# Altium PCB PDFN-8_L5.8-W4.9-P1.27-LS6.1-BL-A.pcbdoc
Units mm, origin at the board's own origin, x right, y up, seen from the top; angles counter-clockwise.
Board outline 18.23 x 19.67 mm, 2 copper layers (Top Layer, Bottom Layer), stack 0 mm thick; 1 components, 0 nets, 9 pads, 0 vias.
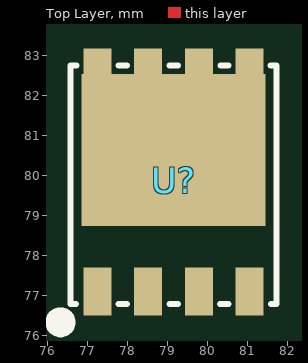
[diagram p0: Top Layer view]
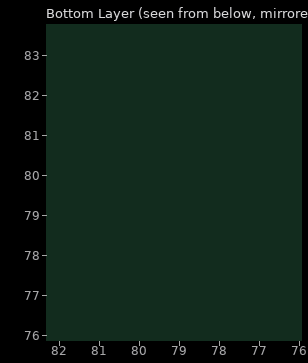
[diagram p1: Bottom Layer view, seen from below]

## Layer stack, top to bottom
Top Layer: signal copper (thickness not stored)
Bottom Layer: signal copper (thickness not stored)

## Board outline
88.08,69.85 69.85,69.85 69.85,89.523 88.08,89.523

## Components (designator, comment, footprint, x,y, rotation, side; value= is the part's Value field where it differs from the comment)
U? "" PDFN-8_L5.8-W4.9-P1.27-LS6.1-BL-A 79.15,79.881 r0 top

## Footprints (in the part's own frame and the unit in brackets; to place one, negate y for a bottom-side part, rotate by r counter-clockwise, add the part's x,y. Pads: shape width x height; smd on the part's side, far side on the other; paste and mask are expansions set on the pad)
PDFN-8_L5.8-W4.9-P1.27-LS6.1-BL-A [mm]
  rect 0.7x1.2 smd paste-100 mask+0.05: 1(-1.905,-2.792) 2(-0.635,-2.792) 3(0.635,-2.792) 4(1.905,-2.792)
  rect 0.7x1 smd paste-100 mask+0.05: 5(1.905,2.792) 6(0.635,2.792) 7(-0.635,2.792) 8(-1.905,2.792)
  rect 4.6x3.8 smd paste-100 mask+0.05: 9(0,0.75)
  silkscreen extent -2.95,-3.68 2.58,2.86

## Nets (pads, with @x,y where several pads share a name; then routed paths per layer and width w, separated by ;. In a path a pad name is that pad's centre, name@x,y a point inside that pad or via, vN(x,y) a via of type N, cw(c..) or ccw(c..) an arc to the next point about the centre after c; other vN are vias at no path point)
pads on no net: U?.1 U?.2 U?.3 U?.4 U?.5 U?.6 U?.7 U?.8 U?.9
